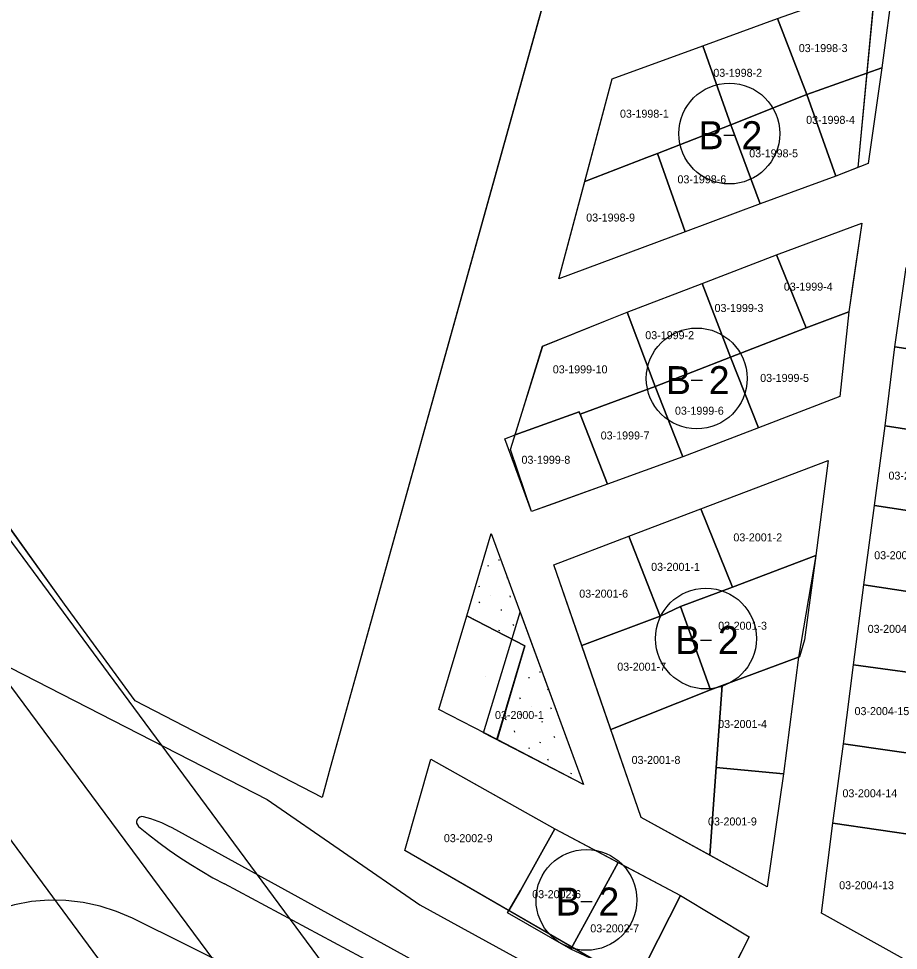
# Model space of a CAD drawing. Extents: x 413946 to 415528, y 4453939 to 4454944.
# Drawn here: x 414198.6 to 414308.6, y 4454644 to 4454760.5 of the extents above; entities that cross this region are included whole.
import ezdxf

# ---------------------------------------------------------------- set-up
doc = ezdxf.new("R2010")
doc.units = 0
for name, color, linetype in [('0_KADASTRO', 7, 'Continuous'), ('HAT_ENERJI_NAKIL_HAT', 7, 'Continuous'), ('KST_ENERJI_NAKIL_HAT', 7, 'Continuous'), ('Level 27', 7, 'Continuous'), ('Level 28', 7, 'Continuous'), ('Level 41', 7, 'Continuous'), ('Level 54', 7, 'Continuous'), ('Level 62', 7, 'Continuous'), ('SEMBOL', 7, 'Continuous'), ('SNR_FONKSIYON', 7, 'Continuous')]:
    doc.layers.add(name, color=color, linetype=linetype)

msp = doc.modelspace()

# ---------------------------------------------------------------- linework, layer by layer
at = {"layer": '0_KADASTRO'}
for points in [[(414096.99, 4454835.77), (414098.7, 4454839.14), (414238.98, 4454892.53), (414254.93, 4454896.1), (414267.24, 4454897.45), (414291.64, 4454897.36), (414301.38, 4454895.97), (414237.57, 4454666.8), (414236.56, 4454663.13), (414213.19, 4454675.19), (414204.39, 4454687.27), (414188.47, 4454709.34), (414167.47, 4454738.38)], [(414293.46, 4454760.45), (414302.86, 4454763.78), (414307.98, 4454765.25), (414306.51, 4454754.31), (414297.15, 4454750.96)], [(414284.15, 4454757.04), (414293.46, 4454760.45), (414297.15, 4454750.96), (414287.63, 4454747.19)], [(414269.4, 4454740.09), (414272.83, 4454752.93), (414284.15, 4454757.04), (414287.63, 4454747.19), (414278.46, 4454743.6), (414277.13, 4454743.09)], [(414297.15, 4454750.96), (414306.51, 4454754.31), (414304.81, 4454742.35), (414300.76, 4454740.77)], [(414287.63, 4454747.19), (414297.15, 4454750.96), (414300.76, 4454740.77), (414291.32, 4454737.31)], [(414278.46, 4454743.6), (414287.63, 4454747.19), (414291.32, 4454737.31), (414281.95, 4454733.82)], [(414266.16, 4454727.95), (414269.4, 4454740.09), (414277.13, 4454743.09), (414278.46, 4454743.6), (414281.95, 4454733.82)], [(414293.35, 4454730.92), (414304, 4454734.89), (414302.86, 4454727.07), (414302.37, 4454723.8), (414297.05, 4454721.82)], [(414284.04, 4454727.36), (414293.35, 4454730.92), (414297.05, 4454721.82), (414287.61, 4454718.14)], [(414308.14, 4454719.43), (414309.53, 4454729.35), (414321.03, 4454727.62), (414319.7, 4454717.69)], [(414274.7, 4454723.77), (414284.04, 4454727.36), (414287.61, 4454718.14), (414278.17, 4454714.49)], [(414260.68, 4454708.42), (414264.12, 4454719.52), (414271.98, 4454722.7), (414274.7, 4454723.77), (414278.17, 4454714.49), (414268.82, 4454711.02), (414268.79, 4454711.07), (414268.69, 4454711.33)], [(414287.61, 4454718.14), (414297.05, 4454721.82), (414302.37, 4454723.8), (414301.26, 4454713.21), (414291.1, 4454709.32)], [(414306.92, 4454709.58), (414308.14, 4454719.43), (414319.7, 4454717.69), (414318.44, 4454707.78)], [(414278.17, 4454714.49), (414287.61, 4454718.14), (414291.1, 4454709.32), (414281.63, 4454705.7)], [(414268.82, 4454711.02), (414278.17, 4454714.49), (414281.63, 4454705.7), (414272.21, 4454702.28)], [(414259.38, 4454707.95), (414260.68, 4454708.42), (414268.69, 4454711.33), (414268.79, 4454711.07), (414268.82, 4454711.02), (414272.21, 4454702.28), (414265.43, 4454699.82), (414262.75, 4454698.85)], [(414305.6, 4454699.59), (414306.92, 4454709.58), (414318.44, 4454707.78), (414317.1, 4454697.86)], [(414283.89, 4454699.2), (414299.82, 4454705.24), (414298.25, 4454693.35), (414287.83, 4454689.41)], [(414304.26, 4454689.71), (414305.6, 4454699.59), (414317.1, 4454697.86), (414315.76, 4454687.96)], [(414274.88, 4454695.77), (414283.89, 4454699.2), (414287.83, 4454689.41), (414281.37, 4454686.99), (414278.82, 4454685.79)], [(414265.54, 4454692.21), (414274.88, 4454695.77), (414278.82, 4454685.79), (414269.03, 4454682.11)], [(414281.37, 4454686.99), (414287.83, 4454689.41), (414298.25, 4454693.35), (414296.85, 4454682.81), (414296.24, 4454680.71), (414296.11, 4454680.66), (414286.54, 4454677.12), (414285.1, 4454676.57)], [(414302.97, 4454679.69), (414304.26, 4454689.71), (414315.76, 4454687.96), (414314.59, 4454678.11)], [(414269.03, 4454682.11), (414278.82, 4454685.79), (414281.37, 4454686.99), (414285.1, 4454676.57), (414272.65, 4454671.62)], [(414256.75, 4454671.21), (414261.32, 4454686.27), (414269.24, 4454664.73)], [(414285.8, 4454666.85), (414286.54, 4454677.12), (414296.11, 4454680.66), (414294.23, 4454666.07)], [(414301.72, 4454669.8), (414302.97, 4454679.69), (414314.59, 4454678.11), (414313.01, 4454668.18)], [(414272.65, 4454671.62), (414285.1, 4454676.57), (414286.54, 4454677.12), (414285.8, 4454666.85), (414285.01, 4454655.89), (414276.45, 4454660.61)], [(414300.37, 4454659.89), (414301.72, 4454669.8), (414313.01, 4454668.18), (414311.78, 4454658.24)], [(414246.91, 4454656.5), (414250.14, 4454667.9), (414254.91, 4454665.22), (414265.66, 4454659.18), (414261.34, 4454651.5), (414259.91, 4454648.98)], [(414285.01, 4454655.89), (414285.8, 4454666.85), (414294.23, 4454666.07), (414292.19, 4454651.94)], [(414298.97, 4454648.65), (414300.37, 4454659.89), (414311.78, 4454658.24), (414310.46, 4454648.27), (414309.61, 4454642.73)], [(414259.75, 4454648.7), (414261.34, 4454651.5), (414265.66, 4454659.18), (414273.58, 4454654.99), (414267.66, 4454644.16)], [(414267.66, 4454644.16), (414273.58, 4454654.99), (414281.36, 4454650.87), (414277.19, 4454642.66), (414275.97, 4454640.27)], [(414277.19, 4454642.66), (414281.36, 4454650.87), (414289.93, 4454645.72), (414285.9, 4454637.8)]]:
    msp.add_lwpolyline(points, close=True, dxfattribs=at)
at = {"layer": 'HAT_ENERJI_NAKIL_HAT'}
msp.add_lwpolyline([(414658.52, 4453939.48), (414647.22, 4454070.23), (413999.88, 4454943.96)], dxfattribs=at)
at = {"layer": 'KST_ENERJI_NAKIL_HAT'}
for p, q in [((414230.56, 4454613.27), (414140.52, 4454735.11)), ((414184.47, 4454712.98), (414213, 4454674.38)), ((414213, 4454674.38), (414249.55, 4454624.92))]:
    msp.add_line(p, q, dxfattribs=at)
at = {"layer": 'Level 27'}
for p, q in [((414305.67, 4454764.59), (414303.49, 4454741.83)), ((414284.15, 4454757.04), (414293.46, 4454760.45)), ((414272.83, 4454752.94), (414284.15, 4454757.04)), ((414303.49, 4454741.83), (414300.76, 4454740.77)), ((414300.76, 4454740.77), (414291.32, 4454737.31)), ((414291.32, 4454737.31), (414281.95, 4454733.82)), ((414293.35, 4454730.92), (414304, 4454734.89)), ((414304, 4454734.89), (414302.37, 4454723.8)), ((414281.95, 4454733.82), (414266.16, 4454727.95)), ((414284.04, 4454727.36), (414293.35, 4454730.92)), ((414308.14, 4454719.43), (414309.53, 4454729.35)), ((414274.7, 4454723.77), (414284.04, 4454727.36)), ((414271.98, 4454722.7), (414274.7, 4454723.77)), ((414302.37, 4454723.8), (414301.26, 4454713.21)), ((414264.13, 4454719.52), (414271.98, 4454722.7)), ((414306.92, 4454709.58), (414308.14, 4454719.43)), ((414301.26, 4454713.21), (414291.1, 4454709.32)), ((414291.1, 4454709.32), (414281.63, 4454705.7)), ((414305.6, 4454699.59), (414306.92, 4454709.58)), ((414281.63, 4454705.7), (414272.21, 4454702.28)), ((414283.89, 4454699.2), (414299.82, 4454705.24)), ((414299.82, 4454705.24), (414298.25, 4454693.35)), ((414272.21, 4454702.28), (414262.75, 4454698.85)), ((414304.26, 4454689.71), (414305.6, 4454699.59)), ((414274.88, 4454695.77), (414283.89, 4454699.2)), ((414265.54, 4454692.21), (414274.88, 4454695.77)), ((414298.25, 4454693.35), (414296.11, 4454680.66)), ((414276.45, 4454660.61), (414265.54, 4454692.21)), ((414302.97, 4454679.69), (414304.26, 4454689.71)), ((414296.11, 4454680.66), (414294.23, 4454666.07)), ((414301.72, 4454669.8), (414302.97, 4454679.69)), ((414300.37, 4454659.89), (414301.72, 4454669.8)), ((414250.14, 4454667.9), (414265.66, 4454659.18)), ((414294.23, 4454666.07), (414292.19, 4454651.94)), ((414292.19, 4454651.94), (414276.45, 4454660.61)), ((414298.97, 4454648.65), (414300.37, 4454659.89)), ((414265.66, 4454659.18), (414281.36, 4454650.87)), ((414281.36, 4454650.87), (414289.93, 4454645.72)), ((414309.61, 4454642.73), (414298.97, 4454648.65)), ((414289.93, 4454645.72), (414284.38, 4454634.82))]:
    msp.add_line(p, q, dxfattribs=at)
at = {"layer": 'Level 28'}
for p, q in [((414301.38, 4454895.97), (414237.57, 4454666.8)), ((414266.16, 4454727.95), (414272.83, 4454752.94)), ((414260.12, 4454706.62), (414264.13, 4454719.52)), ((414204.39, 4454687.27), (414188.47, 4454709.34)), ((414262.75, 4454698.85), (414260.12, 4454706.62)), ((414254.64, 4454685.82), (414257.7, 4454696.12)), ((414257.7, 4454696.12), (414269.24, 4454664.73)), ((414213.19, 4454675.19), (414204.39, 4454687.27)), ((414251.17, 4454674.1), (414254.64, 4454685.82)), ((414236.56, 4454663.13), (414213.19, 4454675.19)), ((414258.45, 4454670.36), (414251.17, 4454674.1)), ((414269.24, 4454664.73), (414258.45, 4454670.36)), ((414246.91, 4454656.5), (414250.14, 4454667.9)), ((414237.57, 4454666.8), (414236.56, 4454663.13)), ((414284.38, 4454634.82), (414246.91, 4454656.5))]:
    msp.add_line(p, q, dxfattribs=at)
at = {"layer": 'Level 41'}
for p, q in [((414258.61, 4454692.82), (414258.74, 4454692.8)), ((414258.61, 4454692.82), (414258.74, 4454692.8)), ((414257.24, 4454692.11), (414257.36, 4454692.08)), ((414257.24, 4454692.11), (414257.36, 4454692.08)), ((414259.74, 4454690.53), (414259.68, 4454690.7)), ((414259.74, 4454690.53), (414259.68, 4454690.7)), ((414256.25, 4454689.38), (414256.18, 4454689.54)), ((414256.25, 4454689.38), (414256.18, 4454689.54)), ((414257.6, 4454688.42), (414257.61, 4454688.42)), ((414257.6, 4454688.42), (414257.61, 4454688.42)), ((414260.12, 4454688.15), (414260.06, 4454688.31)), ((414260.12, 4454688.15), (414260.06, 4454688.31)), ((414256.13, 4454687.58), (414256.26, 4454687.48)), ((414256.13, 4454687.58), (414256.26, 4454687.48)), ((414258.88, 4454686.58), (414259.01, 4454686.56)), ((414258.88, 4454686.58), (414259.01, 4454686.56)), ((414255.51, 4454685.37), (414255.48, 4454685.44)), ((414255.51, 4454685.37), (414255.48, 4454685.44)), ((414260.41, 4454684.72), (414260.54, 4454684.62)), ((414260.41, 4454684.72), (414260.54, 4454684.62)), ((414258.61, 4454684.01), (414258.74, 4454683.99)), ((414258.61, 4454684.01), (414258.74, 4454683.99)), ((414263.72, 4454678.83), (414263.84, 4454678.81)), ((414263.72, 4454678.83), (414263.84, 4454678.81)), ((414262.34, 4454678.12), (414262.47, 4454678.1)), ((414262.34, 4454678.12), (414262.47, 4454678.1)), ((414264.85, 4454676.55), (414264.78, 4454676.71)), ((414264.85, 4454676.55), (414264.78, 4454676.71)), ((414261.35, 4454675.4), (414261.29, 4454675.56)), ((414261.35, 4454675.4), (414261.29, 4454675.56)), ((414262.71, 4454674.43), (414262.72, 4454674.43)), ((414262.71, 4454674.43), (414262.72, 4454674.43)), ((414265.23, 4454674.16), (414265.16, 4454674.33)), ((414265.23, 4454674.16), (414265.16, 4454674.33)), ((414259.44, 4454672.89), (414259.57, 4454672.86)), ((414259.44, 4454672.89), (414259.57, 4454672.86)), ((414261.23, 4454673.59), (414261.36, 4454673.5)), ((414261.23, 4454673.59), (414261.36, 4454673.5)), ((414263.99, 4454672.6), (414264.11, 4454672.57)), ((414263.99, 4454672.6), (414264.11, 4454672.57)), ((414260.65, 4454671.29), (414260.59, 4454671.45)), ((414260.65, 4454671.29), (414260.59, 4454671.45)), ((414265.51, 4454670.73), (414265.64, 4454670.63)), ((414265.51, 4454670.73), (414265.64, 4454670.63)), ((414262.34, 4454669.31), (414262.47, 4454669.29)), ((414262.34, 4454669.31), (414262.47, 4454669.29)), ((414263.72, 4454670.03), (414263.84, 4454670)), ((414263.72, 4454670.03), (414263.84, 4454670)), ((414264.85, 4454667.74), (414264.78, 4454667.9)), ((414264.85, 4454667.74), (414264.78, 4454667.9)), ((414267.59, 4454666.15), (414267.72, 4454666.13)), ((414267.59, 4454666.15), (414267.72, 4454666.13))]:
    msp.add_line(p, q, dxfattribs=at)
at = {"layer": 'Level 54'}
msp.add_line((414256.93, 4454678.24), (414256.93, 4454678.24), dxfattribs=at)
for points in [[(414098.7, 4454839.14), (414238.98, 4454892.53), (414254.93, 4454896.1), (414267.24, 4454897.45), (414291.64, 4454897.36), (414301.38, 4454895.97), (414237.57, 4454666.8), (414236.56, 4454663.13), (414213.19, 4454675.19), (414204.39, 4454687.27), (414188.47, 4454709.34), (414167.47, 4454738.38), (414096.99, 4454835.77), (414098.7, 4454839.14)], [(414303.49, 4454741.83), (414300.76, 4454740.77), (414291.32, 4454737.31), (414281.95, 4454733.82), (414266.16, 4454727.95), (414272.83, 4454752.94), (414284.15, 4454757.04), (414293.46, 4454760.45), (414302.86, 4454763.78), (414305.67, 4454764.59)], [(414302.37, 4454723.8), (414301.26, 4454713.21), (414291.1, 4454709.32), (414281.63, 4454705.7), (414272.21, 4454702.28), (414262.75, 4454698.85), (414260.12, 4454706.62), (414264.13, 4454719.52), (414271.98, 4454722.7), (414274.7, 4454723.77), (414284.04, 4454727.36), (414293.35, 4454730.92), (414304, 4454734.89)], [(414274.88, 4454695.77), (414283.89, 4454699.2), (414299.82, 4454705.24), (414298.25, 4454693.35), (414296.11, 4454680.66), (414294.23, 4454666.07), (414292.19, 4454651.94), (414276.45, 4454660.61), (414265.54, 4454692.21)], [(414251.17, 4454674.1), (414254.64, 4454685.82), (414261.88, 4454682.07), (414258.45, 4454670.36)], [(414289.93, 4454645.72), (414284.38, 4454634.82), (414246.91, 4454656.5), (414250.14, 4454667.9), (414265.66, 4454659.18), (414281.36, 4454650.87)]]:
    msp.add_lwpolyline(points, close=True, dxfattribs=at)
msp.add_lwpolyline([(414309.61, 4454642.73), (414298.97, 4454648.65), (414300.37, 4454659.89), (414301.72, 4454669.8), (414302.97, 4454679.69), (414304.26, 4454689.71), (414305.6, 4454699.59), (414306.92, 4454709.58), (414308.14, 4454719.43), (414309.53, 4454729.35)], dxfattribs=at)
at = {"layer": 'Level 62'}
for p, q in [((414054.26, 4454752.9), (414229.71, 4454662.85)), ((414296.72, 4454615.98), (414217.81, 4454659.31)), ((414295.72, 4454614.14), (414224.35, 4454652.32)), ((414301.28, 4454604.39), (414212.85, 4454648.02))]:
    msp.add_line(p, q, dxfattribs=at)
for points in [[(414229.71, 4454662.85), (414248.79, 4454649.72), (414307.87, 4454617.27), (414329.62, 4454604.9)], [(414214.25, 4454660.71), (414214.02, 4454660.73), (414213.79, 4454660.67), (414213.6, 4454660.54), (414213.46, 4454660.35), (414213.39, 4454660.13), (414213.39, 4454659.9), (414213.48, 4454659.68), (414213.63, 4454659.5)], [(414217.81, 4454659.31), (414217.38, 4454659.54), (414216.95, 4454659.75), (414216.52, 4454659.95), (414216.07, 4454660.13), (414215.62, 4454660.3), (414215.17, 4454660.45), (414214.71, 4454660.59), (414214.25, 4454660.71)], [(414213.63, 4454659.5), (414214.88, 4454658.48), (414216.16, 4454657.49), (414217.46, 4454656.53), (414218.79, 4454655.62), (414220.15, 4454654.74), (414221.52, 4454653.89), (414222.92, 4454653.09), (414224.35, 4454652.32)], [(414212.85, 4454648.02), (414210.87, 4454648.88), (414208.81, 4454649.54), (414206.7, 4454650), (414204.56, 4454650.24), (414202.4, 4454650.28), (414200.25, 4454650.1), (414198.13, 4454649.72), (414196.05, 4454649.13)]]:
    msp.add_lwpolyline(points, dxfattribs=at)
at = {"layer": 'SEMBOL'}
for p, q in [((414286.75, 4454745.88), (414288.15, 4454745.88)), ((414282.68, 4454715.27), (414284.08, 4454715.27)), ((414283.83, 4454682.78), (414285.23, 4454682.78)), ((414268.9, 4454650.11), (414270.3, 4454650.11))]:
    msp.add_line(p, q, dxfattribs=at)
for centre in [(414287.45, 4454746.09), (414283.38, 4454715.48), (414284.53, 4454682.98), (414269.6, 4454650.32)]:
    msp.add_circle(centre, 6.3, dxfattribs=at)
at = {"layer": 'SNR_FONKSIYON'}
for p, q in [((414261.88, 4454682.07), (414254.64, 4454685.82)), ((414258.4, 4454670.35), (414261.88, 4454682.07))]:
    msp.add_line(p, q, dxfattribs=at)

# ---------------------------------------------------------------- texts
at = {"layer": '0_KADASTRO'}
for s, p in [('03-1998-3', (414296.13, 4454756.27)), ('03-1998-2', (414285.45, 4454753.18)), ('03-1998-1', (414273.79, 4454748.07)), ('03-1998-4', (414297.05, 4454747.3)), ('03-1998-5', (414289.94, 4454743.12)), ('03-1998-6', (414280.97, 4454739.87)), ('03-1998-9', (414269.57, 4454735.09)), ('03-1999-4', (414294.27, 4454726.46)), ('03-1999-3', (414285.61, 4454723.79)), ('03-1999-2', (414276.95, 4454720.39)), ('03-1999-10', (414265.39, 4454716.12)), ('03-1999-5', (414291.31, 4454715.05)), ('03-1999-6', (414280.66, 4454710.95)), ('03-1999-7', (414271.38, 4454707.86)), ('03-1999-8', (414261.48, 4454704.82)), ('03-2004-18', (414307.34, 4454702.84)), ('03-2001-2', (414287.96, 4454695.12)), ('03-2004-17', (414305.56, 4454692.89)), ('03-2001-1', (414277.68, 4454691.44)), ('03-2001-6', (414268.7, 4454688.09)), ('03-2001-3', (414286.06, 4454684.08)), ('03-2004-16', (414304.74, 4454683.69)), ('03-2001-7', (414273.45, 4454678.96)), ('03-2000-1', (414258.17, 4454672.92)), ('03-2004-15', (414303.1, 4454673.41)), ('03-2001-4', (414286.06, 4454671.8)), ('03-2001-8', (414275.24, 4454667.31)), ('03-2004-14', (414301.59, 4454663.14)), ('03-2001-9', (414284.79, 4454659.62)), ('03-2002-9', (414251.78, 4454657.53)), ('03-2004-13', (414301.18, 4454651.65)), ('03-2002-6', (414262.82, 4454650.53)), ('03-2002-7', (414270.08, 4454646.26))]:
    msp.add_text(s, height=1, dxfattribs=at).set_placement(p)
at = {"layer": 'SEMBOL'}
for s, p in [('B', (414283.61, 4454744.13)), ('2', (414288.96, 4454744.13)), ('B', (414279.53, 4454713.52)), ('2', (414284.88, 4454713.52)), ('B', (414280.68, 4454681.03)), ('2', (414286.03, 4454681.03)), ('B', (414265.75, 4454648.36)), ('2', (414271.1, 4454648.36))]:
    msp.add_text(s, height=3.5, dxfattribs=at).set_placement(p)

doc.saveas('drawing.dxf')
